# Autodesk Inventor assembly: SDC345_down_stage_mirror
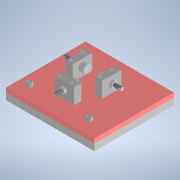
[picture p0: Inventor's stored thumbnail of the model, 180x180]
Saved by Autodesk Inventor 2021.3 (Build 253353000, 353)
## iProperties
Created: 2022-02
Part Number: SDC345_down_stage_mirror
Document SubType Name: Assembly
Designer: kengo
Author: kengo
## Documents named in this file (8)
- C:\Users\kengo\Documents\S2S_frame\SDC345\frame_misumi_ver12\stage\SDC345_down_stage_mirror.iam
- C:\Users\kengo\Documents\S2S_frame\SDC345\frame_misumi_ver12\stage\SDC3_Delstage.ipt
- C:\Users\kengo\Documents\S2S_frame\SDC345\frame_misumi_ver12\stage\SDC345_Alstage_mirror.ipt
- C:\Users\kengo\Documents\S2S_frame\SDC345\frame_misumi_ver12\stage\SCB8-15.ipt
- C:\Users\kengo\Documents\S2S_frame\SDC345\frame_misumi_ver12\stage\SCB8-35.ipt
- C:\Users\kengo\Documents\S2S_frame\SDC345\frame_misumi_ver12\stage\AJSN8-20.ipt
- C:\Users\kengo\Documents\S2S_frame\SDC345\frame_misumi_ver12\stage\SCB6-50.ipt
- C:\Users\kengo\Documents\S2S_frame\SDC345\frame_misumi_ver12\stage\UNST8-40.iam
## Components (18 placed, 7 different names)
1. SDC3_Delstage:1 — メイト:1, フラッシュ:1, フラッシュ:2, 回転:2, 回転:3, 回転:4, 回転:5, 回転:6, 回転:7, 回転:12, 回転:15
2. SDC345_Alstage_mirror:1 — 回転:1, メイト:1, フラッシュ:1, フラッシュ:2
3. SCB8-15:1 — 回転:1
4. SCB8-35:1 — 回転:2
5. SCB8-35:2 — 回転:3
6. SCB8-35:3 — 回転:4
7. AJSN8-20:1 — 回転:5, 回転:13, 回転:14, 回転:18
8. AJSN8-20:2 — 回転:6, 回転:10, 回転:11, 回転:16
9. AJSN8-20:3 — 回転:7, 回転:8, 回転:9, 回転:17
10. SCB6-50:1 — 回転:8
11. SCB6-50:2 — 回転:9
12. SCB6-50:3 — 回転:10
13. SCB6-50:4 — 回転:11, 回転:12
14. SCB6-50:5 — 回転:13
15. SCB6-50:6 — 回転:14, 回転:15
16. UNST8-40:1 [sub-assembly] — 回転:16
17. UNST8-40:2 [sub-assembly] — 回転:17
18. UNST8-40:3 [sub-assembly] — 回転:18
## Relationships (21: RevoluteJoint 18, Flush 2, Mate 1)
- 回転:1 [RevoluteJoint]: SDC345_Alstage_mirror:1 ↔ SCB8-15:1
- メイト:1 [Mate]: SDC3_Delstage:1 ↔ SDC345_Alstage_mirror:1
- フラッシュ:1 [Flush]: SDC3_Delstage:1 ↔ SDC345_Alstage_mirror:1
- フラッシュ:2 [Flush]: SDC3_Delstage:1 ↔ SDC345_Alstage_mirror:1
- 回転:2 [RevoluteJoint]: SDC3_Delstage:1 ↔ SCB8-35:1
- 回転:3 [RevoluteJoint]: SDC3_Delstage:1 ↔ SCB8-35:2
- 回転:4 [RevoluteJoint]: SDC3_Delstage:1 ↔ SCB8-35:3
- 回転:5 [RevoluteJoint]: SDC3_Delstage:1 ↔ AJSN8-20:1
- 回転:6 [RevoluteJoint]: SDC3_Delstage:1 ↔ AJSN8-20:2
- 回転:7 [RevoluteJoint]: SDC3_Delstage:1 ↔ AJSN8-20:3
- 回転:8 [RevoluteJoint]: AJSN8-20:3 ↔ SCB6-50:1
- 回転:9 [RevoluteJoint]: AJSN8-20:3 ↔ SCB6-50:2
- 回転:10 [RevoluteJoint]: AJSN8-20:2 ↔ SCB6-50:3
- 回転:11 [RevoluteJoint]: AJSN8-20:2 ↔ SCB6-50:4
- 回転:12 [RevoluteJoint]: SDC3_Delstage:1 ↔ SCB6-50:4
- 回転:13 [RevoluteJoint]: AJSN8-20:1 ↔ SCB6-50:5
- 回転:14 [RevoluteJoint]: AJSN8-20:1 ↔ SCB6-50:6
- 回転:15 [RevoluteJoint]: SDC3_Delstage:1 ↔ SCB6-50:6
- 回転:16 [RevoluteJoint]: AJSN8-20:2 ↔ UNST8-40:1
- 回転:17 [RevoluteJoint]: AJSN8-20:3 ↔ UNST8-40:2
- 回転:18 [RevoluteJoint]: AJSN8-20:1 ↔ UNST8-40:3
